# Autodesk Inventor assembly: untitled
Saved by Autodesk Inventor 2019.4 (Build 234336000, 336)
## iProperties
Created: 2020-01
Part Number: untitled
Document SubType Name: Assembly
Designer: Administrator
Title: untitled v4
Author: Administrator
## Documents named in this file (2)
- c:\worker\convert-fusion-r01\tmp\job-1\61\output\files\aee60a31-d91c-4752-9293-a14cfbf1decc\untitled v4.iam
- c:\worker\convert-fusion-r01\tmp\job-1\61\output\files\aee60a31-d91c-4752-9293-a14cfbf1decc\PCB Component.iam
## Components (1 placed, 1 different names)
1. PCB Component:1 [sub-assembly]
